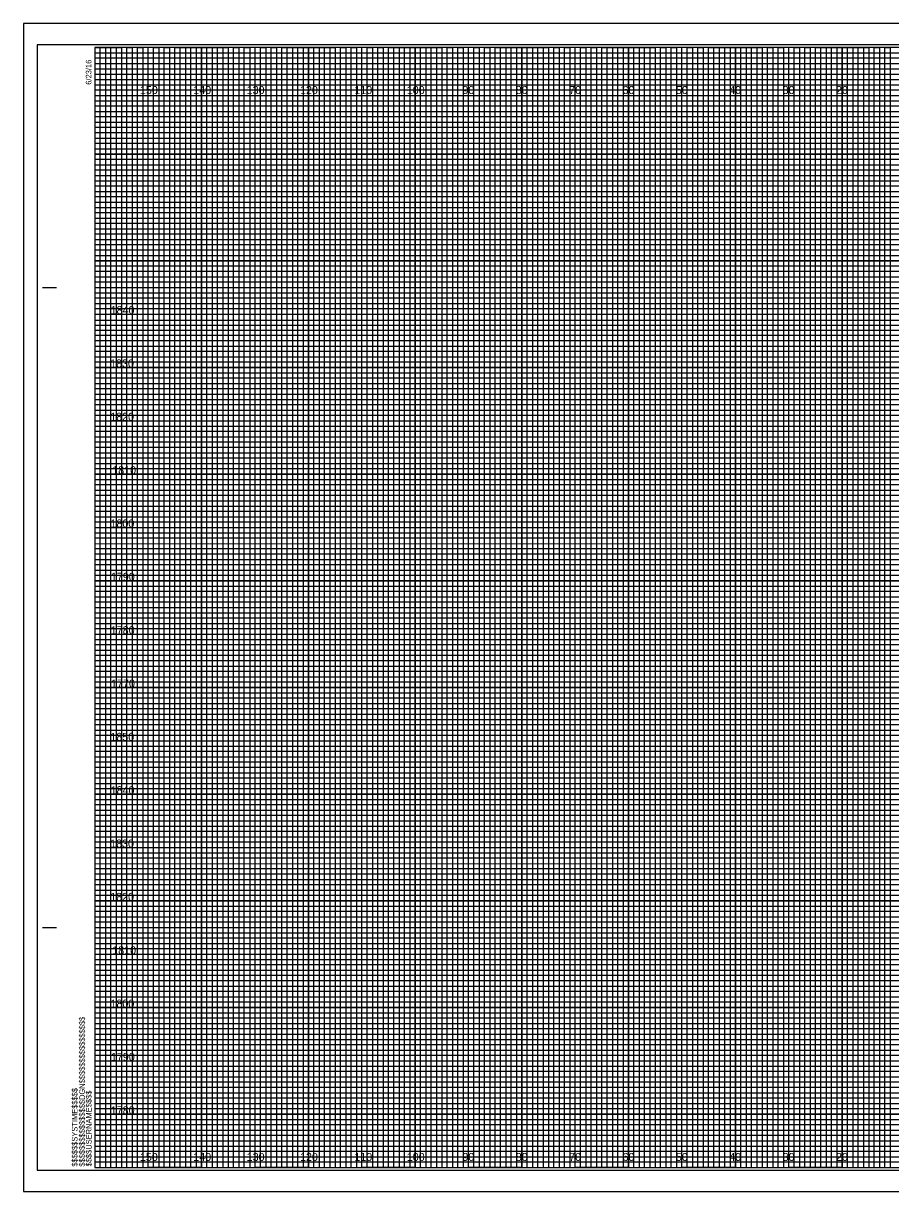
# Model space of a CAD drawing. Extents: x -13 to 323, y -5 to 654.
# Drawn here: x -13.4 to 149.1, y -4.5 to 214.5 of the extents above; entities that cross this region are included whole.
import ezdxf

# ---------------------------------------------------------------- set-up
doc = ezdxf.new("R2010")
doc.units = 0
for name, color, linetype in [('Prop XS DDE', 7, 'Continuous'), ('Prop XS Earthwork Shape', 7, 'Continuous'), ('Raster_Level_0', 7, 'Continuous'), ('Scratch_Level_3', 7, 'Continuous'), ('Sheet Cross Section CELL', 7, 'Continuous'), ('Sheet Cross Section Grid Minor 1 CELL', 7, 'Continuous'), ('Sheet Cross Section Grid Minor 2 CELL', 7, 'Continuous'), ('Sheet Cutting Line CELL', 7, 'Continuous'), ('Sheet DOT Grid CELL', 7, 'Continuous'), ('Sheet Plot Border Inside CELL', 7, 'Continuous'), ('Sheet Plot Border Outside CELL', 7, 'Continuous')]:
    doc.layers.add(name, color=color, linetype=linetype)

msp = doc.modelspace()

# ---------------------------------------------------------------- linework, layer by layer
at = {"layer": 'Prop XS DDE'}
for points in [[(0, 210), (5, 210), (5, 0), (15, 0), (15, 210), (25, 210), (25, 0), (35, 0), (35, 210), (45, 210), (45, 0), (55, 0), (55, 210), (65, 210), (65, 0), (75, 0), (75, 210), (85, 210), (85, 0), (95, 0), (95, 210), (105, 210), (105, 0), (115, 0), (115, 210), (125, 210), (125, 0), (135, 0), (135, 210), (145, 210), (145, 0), (155, 0)], [(0, 205), (275, 205)], [(0, 185), (320, 185), (320, 195), (0, 195)], [(0, 165), (320, 165), (320, 175), (0, 175)], [(0, 145), (320, 145), (320, 155), (0, 155)], [(0, 125), (320, 125), (320, 135), (0, 135)], [(0, 105), (320, 105), (320, 115), (0, 115)], [(0, 85), (320, 85), (320, 95), (0, 95)], [(0, 65), (320, 65), (320, 75), (0, 75)], [(0, 45), (320, 45), (320, 55), (0, 55)], [(0, 25), (320, 25), (320, 35), (0, 35)], [(0, 5), (320, 5), (320, 15), (0, 15)]]:
    msp.add_lwpolyline(points, dxfattribs=at)
at = {"layer": 'Prop XS Earthwork Shape'}
for p, q in [((10, 210), (0, 210)), ((10, 0), (10, 210)), ((30, 210), (20, 210)), ((20, 210), (20, 0)), ((30, 0), (30, 210)), ((50, 210), (40, 210)), ((40, 210), (40, 0)), ((50, 0), (50, 210)), ((70, 210), (60, 210)), ((60, 210), (60, 0)), ((70, 0), (70, 210)), ((90, 210), (80, 210)), ((80, 210), (80, 0)), ((90, 0), (90, 210)), ((110, 210), (100, 210)), ((100, 210), (100, 0)), ((110, 0), (110, 210)), ((130, 210), (120, 210)), ((120, 210), (120, 0)), ((130, 0), (130, 210)), ((150, 210), (140, 210)), ((140, 210), (140, 0)), ((20, 0), (10, 0)), ((40, 0), (30, 0)), ((60, 0), (50, 0)), ((80, 0), (70, 0)), ((100, 0), (90, 0)), ((120, 0), (110, 0)), ((140, 0), (130, 0))]:
    msp.add_line(p, q, dxfattribs=at)
for points in [[(0, 200), (320, 200), (320, 190), (0, 190)], [(0, 180), (320, 180), (320, 170), (0, 170)], [(0, 160), (320, 160), (320, 150), (0, 150)], [(0, 140), (320, 140), (320, 130), (0, 130)], [(0, 120), (320, 120), (320, 110), (0, 110)], [(0, 100), (320, 100), (320, 90), (0, 90)], [(0, 80), (320, 80), (320, 70), (0, 70)], [(0, 60), (320, 60), (320, 50), (0, 50)], [(0, 40), (320, 40), (320, 30), (0, 30)], [(0, 20), (320, 20), (320, 10), (0, 10)]]:
    msp.add_lwpolyline(points, dxfattribs=at)
at = {"layer": 'Sheet Cross Section CELL'}
for p, q in [((-9.8, 165), (-7.3, 165)), ((-9.7, 165), (-7.2, 165)), ((-9.8, 45), (-7.3, 45)), ((-9.7, 45), (-7.2, 45)), ((0, 0), (0, 0)), ((0, 0), (0, 0)), ((0, 0), (0, 0)), ((0, 0), (0, 0)), ((0, 0), (0, 0)), ((0, 0), (0, 0)), ((0, 0), (0, 0))]:
    msp.add_line(p, q, dxfattribs=at)
msp.add_lwpolyline([(320, 210), (0, 210), (0, 0), (320, 0)], close=True, dxfattribs=at)
at = {"layer": 'Sheet Cross Section Grid Minor 1 CELL'}
for p, q in [((0, 209), (260, 209)), ((260, 207.98), (0, 207.98)), ((0, 207.98), (0, 207)), ((0, 207), (260, 207)), ((260, 205.89), (0, 205.89)), ((0, 205.89), (0, 204)), ((0, 204), (320, 204))]:
    msp.add_line(p, q, dxfattribs=at)
for points in [[(0, 203), (270, 203), (320, 203), (320, 202), (0, 202)], [(0, 201), (320, 201), (320, 199), (0, 199)], [(0, 198), (320, 198), (320, 197), (0, 196.98)], [(0, 196), (320, 196), (320, 194), (0, 194)], [(0, 193), (320, 193), (320, 192), (0, 192)], [(0, 191), (320, 191), (320, 189), (0, 189)], [(0, 188), (320, 188), (320, 187), (0, 187)], [(0, 186), (320, 186), (320, 184), (0, 184)], [(0, 183), (320, 183), (320, 182), (0, 182)], [(0, 181), (320, 181), (320, 179), (0, 179)], [(0, 178), (320, 178), (320, 177), (0, 177)], [(0, 176), (320, 176), (320, 173.95), (320, 173), (320, 172), (0, 172)], [(0, 174), (320, 174), (320, 173), (0, 173)], [(0, 171), (320, 171), (320, 169), (0, 169.03)], [(0, 169.03), (320, 169), (320, 168), (0, 168)], [(0, 167), (320, 167), (320, 166), (0, 166)], [(0, 164), (320, 164), (320, 163), (0, 163)], [(0, 162), (320, 162), (320, 161), (0, 161)], [(-0.07, 158.89), (320, 158.89), (320, 157.88), (-0.07, 157.88)], [(0, 157), (320, 157), (320, 156), (0, 156)], [(0, 154), (320, 154), (320, 153), (0, 153)], [(0, 152), (320, 152), (320, 151), (0, 151)], [(0, 149), (320, 149), (320, 148), (0, 148)], [(0, 147), (320, 147), (320, 146), (0, 146)], [(0, 144), (320, 144), (320, 143), (0, 143)], [(0, 142), (320, 142), (320, 141), (0, 141)], [(0, 139), (320, 139), (319.99, 137.98), (0, 138)], [(0, 137), (320, 137), (320, 136), (0, 136)], [(0, 134), (320, 134), (320, 133), (0, 133)], [(0, 132), (320, 132), (320, 131), (0, 131)], [(0, 129), (320, 129), (320, 128), (0, 128)], [(0, 127), (320, 127), (320, 126), (0, 126)], [(0, 124), (320, 124), (320, 123), (0, 123)], [(0, 122), (320, 122), (320, 121), (0, 121)], [(0, 119), (320, 119), (320, 118), (0, 118)], [(0, 116.99), (320.07, 116.91), (320, 116), (0, 116)], [(0, 114), (320, 114), (320, 113), (0, 113)], [(0, 112), (320, 112), (320, 111), (0, 111)], [(0, 109), (320, 109), (320, 108), (0, 108)], [(0, 107), (320, 107), (320, 106), (0, 106)], [(0, 104), (320, 104), (320, 103), (0, 103)], [(0, 102), (320, 102), (320, 101), (0, 101)], [(0, 99), (320, 99), (320, 98), (0, 98)], [(0, 97), (320, 97), (320, 96), (0, 96)], [(0, 94), (320, 94), (320, 93), (0, 93)], [(0, 92), (320, 92), (320, 91), (0, 91)], [(0, 89), (320, 89), (320, 88), (0, 88)], [(0, 87), (320, 87), (320, 86), (0, 86)], [(0, 84), (320, 84), (320, 83), (0, 83)], [(0, 82), (320, 82), (320, 81), (0, 81)], [(0, 79), (320, 79), (319.99, 77.98), (0, 78)], [(0, 77), (320, 77), (320, 76), (0, 76)], [(0, 74), (320, 74), (320, 73), (0, 73)], [(0, 72), (320, 72), (320, 71), (0, 71)], [(0, 69), (320, 69), (320, 68), (0, 68)], [(0, 67), (320, 67), (320, 66), (0, 66)], [(0, 64), (320, 64), (320, 63), (0, 63)], [(0, 62), (320, 62), (320, 61), (0, 61)], [(0, 59), (320, 59), (320, 58), (0, 58)], [(0, 56.99), (320.07, 56.91), (320, 56), (0, 56)], [(0, 54), (320, 54), (320, 53), (0, 53)], [(0, 52), (320, 52), (320, 51), (0, 51)], [(0, 49), (320, 49), (320, 48), (0, 48)], [(0, 47), (320, 47), (320, 46), (0, 46)], [(0, 44), (320, 44), (320, 43), (0, 43)], [(0, 42), (320, 42), (320, 41), (0, 41)], [(0, 39), (320, 39), (320, 38), (0, 38)], [(0, 37), (320, 37), (320, 36), (0, 36)], [(0, 34), (320, 34), (320, 33), (0, 33)], [(0, 32), (320, 32), (320, 31), (0, 31)], [(0, 29), (320, 29), (320, 28), (0, 28)], [(0, 27), (320, 27), (320, 26), (0, 26)], [(0, 24), (320, 24), (320, 23), (0, 23)], [(0, 22), (320, 22), (320, 21), (0, 21)], [(0, 19), (320, 19), (320, 18), (0, 18)], [(0, 17), (320, 17), (320, 16), (0, 16)], [(0, 14), (320, 14), (320, 13), (0, 13)], [(0, 12), (320, 12), (320, 11), (0, 11)], [(0, 9), (320, 9), (320, 8), (0, 8)], [(0, 7), (320, 7), (320, 6), (0, 6)], [(0, 4), (320, 4), (320, 3), (0, 3)], [(0, 2), (320, 2), (320, 1), (0, 1)]]:
    msp.add_lwpolyline(points, dxfattribs=at)
at = {"layer": 'Sheet Cross Section Grid Minor 2 CELL'}
for points in [[(0, 0), (1, 0), (1, 210), (2, 210), (2, 0)], [(2, 0), (3, 0), (3, 210), (4, 210), (4, 0)], [(5, 0), (6, 0), (6, 210), (7, 210), (7, 0)], [(7, 0), (8, 0), (8, 210), (9, 210), (9, 0)], [(10, 0), (11, 0), (11, 210), (12, 210), (12, 0)], [(12, 0), (13, 0), (13, 210), (14, 210), (14, 0)], [(15, 0), (16, 0), (16, 210), (17, 210), (17, 0)], [(17, 0), (18, 0), (18, 210), (19, 210), (19, 0)], [(20, 0), (21, 0), (21, 210), (22, 210), (22, 0)], [(22, 0), (23, 0), (23, 210), (24, 210), (24, 0)], [(25, 0), (26, 0), (26, 210), (27, 210), (27, 0)], [(27, 0), (28, 0), (28, 210), (29, 210), (29, 0)], [(30, 0), (31, 0), (31, 210), (32, 210), (32, 0)], [(32, 0), (33, 0), (33, 210), (34, 210), (34, 0)], [(35, 0), (36, 0), (36, 210), (37, 210), (37, 0)], [(37, 0), (38, 0), (38, 210), (39, 210), (39, 0)], [(40, 0), (41, 0), (41, 210), (42, 210), (42, 0)], [(42, 0), (43, 0), (43, 210), (44, 210), (44, 0)], [(45, 0), (46, 0), (46, 210), (47, 210), (47, 0)], [(47, 0), (48, 0), (48, 210), (49, 210), (49, 0)], [(50, 0), (51, 0), (51, 210), (52, 210), (52, 0)], [(52, 0), (53, 0), (53, 210), (54, 210), (54, 0)], [(55, 0), (56, 0), (56, 210), (57, 210), (57, 0)], [(57, 0), (58, 0), (58, 210), (59, 210), (59, 0)], [(60, 0), (61, 0), (61, 210), (62, 210), (62, 0)], [(62, 0), (63, 0), (63, 210), (64, 210), (64, 0)], [(65, 0), (66, 0), (66, 210), (67, 210), (67, 0)], [(67, 0), (68, 0), (68, 210), (69, 210), (69, 0)], [(70, 0), (71, 0), (71, 210), (72, 210), (72, 0)], [(72, 0), (73, 0), (73, 210), (74, 210), (74, 0)], [(75, 0), (76, 0), (76, 210), (77, 210), (77, 0)], [(77, 0), (78, 0), (78, 210), (79, 210), (79, 0)], [(80, 0), (81, 0), (81, 210), (82, 210), (82, 0)], [(82, 0), (83, 0), (83, 210), (84, 210), (84, 0)], [(85, 0), (86, 0), (86, 210), (87, 210), (87, 0)], [(87, 0), (88, 0), (88, 210), (89, 210), (89, 0)], [(90, 0), (91, 0), (91, 210), (92, 210), (92, 0)], [(92, 0), (93, 0), (93, 210), (94, 210), (94, 0)], [(95, 0), (96, 0), (96, 210), (97, 210), (97, 0)], [(97, 0), (98, 0), (98, 210), (99, 210), (99, 0)], [(100, 0), (101, 0), (101, 210), (102, 210), (102, 0)], [(102, 0), (103, 0), (103, 210), (104, 210), (104, 0)], [(105, 0), (106, 0), (106, 210), (107, 210), (107, 0)], [(107, 0), (108, 0), (108, 210), (109, 210), (109, 0)], [(110, 0), (111, 0), (111, 210), (112, 210), (112, 0)], [(112, 0), (113, 0), (113, 210), (114, 210), (114, 0)], [(115, 0), (116, 0), (116, 210), (117, 210), (117, 0)], [(117, 0), (118, 0), (118, 210), (119, 210), (119, 0)], [(120, 0), (121, 0), (121, 210), (122, 210), (122, 0)], [(122, 0), (123, 0), (123, 210), (124, 210), (124, 0)], [(125, 0), (126, 0), (126, 210), (127, 210), (127, 0)], [(127, 0), (128, 0), (128, 210), (129, 210), (129, 0)], [(130, 0), (131, 0), (131, 210), (132, 210), (132, 0)], [(132, 0), (133, 0), (133, 210), (134, 210), (134, 0)], [(135, 0), (136, 0), (136, 210), (137, 210), (137, 0)], [(137, 0), (138, 0), (138, 210), (139, 210), (139, 0)], [(140, 0), (141, 0), (141, 210), (142, 210), (142, 0)], [(142, 0), (143, 0), (143, 210), (144, 210), (144, 0)], [(145, 0), (146, 0), (146, 210), (147, 210), (147, 0)], [(147, 0), (148, 0), (148, 210), (149, 210), (149, 0)]]:
    msp.add_lwpolyline(points, dxfattribs=at)
at = {"layer": 'Sheet Cutting Line CELL'}
for p, q in [((323.3, 214.5), (-13.4, 214.5)), ((-13.4, 214.5), (-13.4, -4.5)), ((-13.4, -4.5), (323.3, -4.5))]:
    msp.add_line(p, q, dxfattribs=at)
at = {"layer": 'Sheet DOT Grid CELL'}
for p, q in [((10, 0), (10, 210)), ((20, 0), (20, 210)), ((30, 0), (30, 210)), ((40, 0), (40, 210)), ((50, 0), (50, 210)), ((60, 0), (60, 210)), ((70, 0), (70, 210)), ((80, 0), (80, 210)), ((90, 0), (90, 210)), ((100, 0), (100, 210)), ((110, 0), (110, 210)), ((120, 0), (120, 210)), ((130, 0), (130, 210)), ((140, 0), (140, 210)), ((0, 200), (320, 200)), ((0, 190), (320, 190)), ((0, 180), (320, 180)), ((0, 170), (320, 170)), ((0, 160), (320, 160)), ((0, 150), (320, 150)), ((0, 140), (320, 140)), ((0, 130), (320, 130)), ((0, 120), (320, 120)), ((0, 110), (320, 110)), ((0, 100), (320, 100)), ((0, 90), (320, 90)), ((0, 80), (320, 80)), ((0, 70), (320, 70)), ((0, 60), (320, 60)), ((0, 50), (320, 50)), ((0, 40), (320, 40)), ((0, 30), (320, 30)), ((0, 20), (320, 20)), ((0, 10), (320, 10))]:
    msp.add_line(p, q, dxfattribs=at)
at = {"layer": 'Sheet Plot Border Inside CELL'}
msp.add_lwpolyline([(-10.8, -0.5), (322.4, -0.5), (322.4, 210.5), (-10.8, 210.5)], close=True, dxfattribs=at)
at = {"layer": 'Sheet Plot Border Outside CELL'}
msp.add_lwpolyline([(-13.4, -4.5), (323.3, -4.5), (323.3, 214.5), (-13.4, 214.5)], close=True, dxfattribs=at)

# ---------------------------------------------------------------- texts
at = {"layer": 'Raster_Level_0'}
for s, p in [('150', (8.44, 201.25)), ('140', (18.44, 201.25)), ('130', (28.44, 201.25)), ('120', (38.44, 201.25)), ('110', (48.62, 201.25)), ('100', (58.44, 201.25)), ('90', (68.86, 201.25)), ('80', (78.86, 201.25)), ('70', (88.86, 201.25)), ('60', (98.86, 201.25)), ('50', (108.86, 201.25)), ('40', (118.86, 201.25)), ('30', (128.86, 201.25)), ('20', (138.86, 201.25)), ('150', (8.44, 1.25)), ('140', (18.44, 1.25)), ('130', (28.44, 1.25)), ('120', (38.44, 1.25)), ('110', (48.62, 1.25)), ('100', (58.44, 1.25)), ('90', (68.86, 1.25)), ('80', (78.86, 1.25)), ('70', (88.86, 1.25)), ('60', (98.86, 1.25)), ('50', (108.86, 1.25)), ('40', (118.86, 1.25)), ('30', (128.86, 1.25)), ('20', (138.86, 1.25))]:
    msp.add_text(s, height=1.5, dxfattribs=at).set_placement(p)
at = {"layer": 'Scratch_Level_3'}
for s, p in [('1840', (2.95, 160)), ('1830', (2.86, 150)), ('1820', (2.87, 140)), ('1810', (3.25, 130)), ('1800', (2.92, 120)), ('1790', (3, 110)), ('1780', (2.98, 100)), ('1770', (3.04, 90)), ('1850', (2.9, 80)), ('1840', (2.95, 70)), ('1830', (2.86, 60)), ('1820', (2.87, 50)), ('1810', (3.25, 40)), ('1800', (2.92, 30)), ('1790', (3, 20)), ('1780', (2.98, 10))]:
    msp.add_text(s, height=1.5, dxfattribs=at).set_placement(p)
at = {"layer": 'Sheet Cross Section CELL'}
for s, p in [('6/23/16', (-0.65, 203)), ('$$$$$$$$$$$$$$$$DGN$$$$$$$$$$$$$$$$', (-1.88, 0.18)), ('$$$$$$SYSTIME$$$$$', (-3.26, 0.18)), ('$$$$USERNAME$$$$', (-0.62, 0.23))]:
    msp.add_text(s, height=1.05, rotation=90, dxfattribs=at).set_placement(p)

doc.saveas('drawing.dxf')
